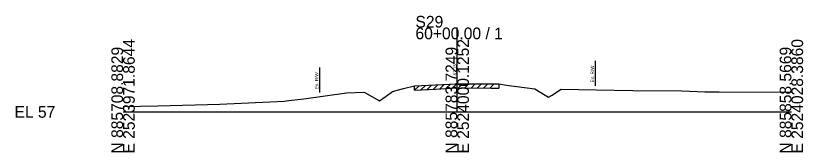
# Model space of a CAD drawing. Extents: x -26 to 163, y -10 to 4024.
# Drawn here: x -25.7 to 162.8, y 990.3 to 1023.1 of the extents above; entities that cross this region are included whole.
import ezdxf

# ---------------------------------------------------------------- set-up
doc = ezdxf.new("R2010")
doc.units = 0
for name, color, linetype in [('RD_GPK_XS_Cell', 7, 'Continuous'), ('RD_XS_ExGround', 7, 'Continuous'), ('RD_XS_ExPaveRet', 7, 'Continuous'), ('RD_XS_ExRW', 7, 'Continuous'), ('RD_XS_TX_Elev_EX', 7, 'Continuous')]:
    doc.layers.add(name, color=color, linetype=linetype)

msp = doc.modelspace()

# ---------------------------------------------------------------- linework, layer by layer
at = {"layer": 'RD_GPK_XS_Cell'}
for p, q in [((80, 1000), (80, 1020.24)), ((0, 1000), (80, 1000)), ((80, 1000), (160, 1000))]:
    msp.add_line(p, q, dxfattribs=at)
at = {"layer": 'RD_XS_ExGround'}
for p, q in [((62.96, 1003.74), (64.48, 1004.9)), ((64.48, 1004.9), (67.14, 1005.58)), ((67.14, 1005.58), (69.81, 1006.22)), ((69.81, 1006.22), (74.8, 1006.49)), ((74.8, 1006.49), (79.85, 1006.75)), ((79.85, 1006.75), (88.14, 1006.72)), ((88.14, 1006.72), (89.93, 1006.73)), ((89.93, 1006.73), (91.78, 1006.45)), ((91.78, 1006.45), (98.57, 1005.51)), ((98.57, 1005.51), (101.04, 1003.99)), ((102.59, 1003.97), (104.92, 1005.43)), ((104.92, 1005.43), (117.56, 1005.22)), ((117.56, 1005.22), (122.04, 1005.14)), ((122.04, 1005.14), (133.79, 1005.04)), ((133.79, 1005.04), (139.28, 1004.82)), ((39.7, 1002.74), (43.26, 1003.17)), ((43.26, 1003.17), (53.46, 1004.56)), ((53.46, 1004.56), (57.73, 1004.75)), ((57.73, 1004.75), (59.53, 1003.7)), ((59.53, 1003.7), (61.42, 1002.64)), ((61.42, 1002.64), (62.96, 1003.74)), ((101.04, 1003.99), (101.82, 1003.5)), ((101.82, 1003.5), (102.59, 1003.97)), ((139.28, 1004.82), (142.67, 1004.82)), ((142.67, 1004.82), (160, 1004.76)), ((0, 1001.29), (8.34, 1001.48)), ((8.34, 1001.48), (23.14, 1001.88)), ((23.14, 1001.88), (38.57, 1002.6)), ((38.57, 1002.6), (39.7, 1002.74))]:
    msp.add_line(p, q, dxfattribs=at)
at = {"layer": 'RD_XS_ExPaveRet'}
for p, q in [((69.81, 1005.22), (70.87, 1006.28)), ((69.81, 1005.22), (69.81, 1006.22)), ((69.81, 1005.22), (74.8, 1005.49)), ((71.31, 1005.3), (72.37, 1006.36)), ((72.81, 1005.38), (73.87, 1006.44)), ((74.31, 1005.46), (75.37, 1006.52)), ((74.8, 1005.49), (79.85, 1005.75)), ((75.81, 1005.54), (76.87, 1006.59)), ((77.31, 1005.62), (78.37, 1006.67)), ((78.81, 1005.69), (79.87, 1006.75)), ((79.85, 1005.75), (88.14, 1005.72)), ((80.31, 1005.75), (81.31, 1006.74)), ((81.81, 1005.74), (82.81, 1006.74)), ((83.31, 1005.73), (84.31, 1006.73)), ((84.81, 1005.73), (85.81, 1006.72)), ((86.31, 1005.72), (87.31, 1006.72)), ((87.81, 1005.72), (88.82, 1006.72)), ((88.14, 1005.72), (89.93, 1005.73)), ((89.93, 1006.73), (89.93, 1005.73))]:
    msp.add_line(p, q, dxfattribs=at)
at = {"layer": 'RD_XS_ExRW'}
for p, q in [((47, 1010.68), (47, 1004.68)), ((113, 1012.29), (113, 1006.29))]:
    msp.add_line(p, q, dxfattribs=at)

# ---------------------------------------------------------------- texts
at = {"layer": 'RD_GPK_XS_Cell'}
for s, p in [('S29', (70, 1020.24)), ('60+00.00 / 1', (70, 1017.44)), ('EL 57', (-26, 998.6))]:
    msp.add_text(s, height=2.8, dxfattribs=at).set_placement(p)
for s, p in [('E 2523971.8644', (2.8, 990)), ('E 2524000.1252', (82.8, 990)), ('E 2524028.3860', (162.8, 990)), ('N 885708.8829', (0, 990)), ('N 885783.7249', (80, 990)), ('N 885858.5669', (160, 990))]:
    msp.add_text(s, height=2.8, rotation=90, dxfattribs=at).set_placement(p)
at = {"layer": 'RD_XS_ExRW'}
for p in [(112.75, 1007.08), (46.75, 1005.46)]:
    msp.add_text('Ex. R/W ', height=0.8, rotation=90, dxfattribs=at).set_placement(p)
at = {"layer": 'RD_XS_TX_Elev_EX'}
msp.add_text('63.75', height=0.8, rotation=90, dxfattribs=at).set_placement((79.9, 1008.75))

doc.saveas('drawing.dxf')
